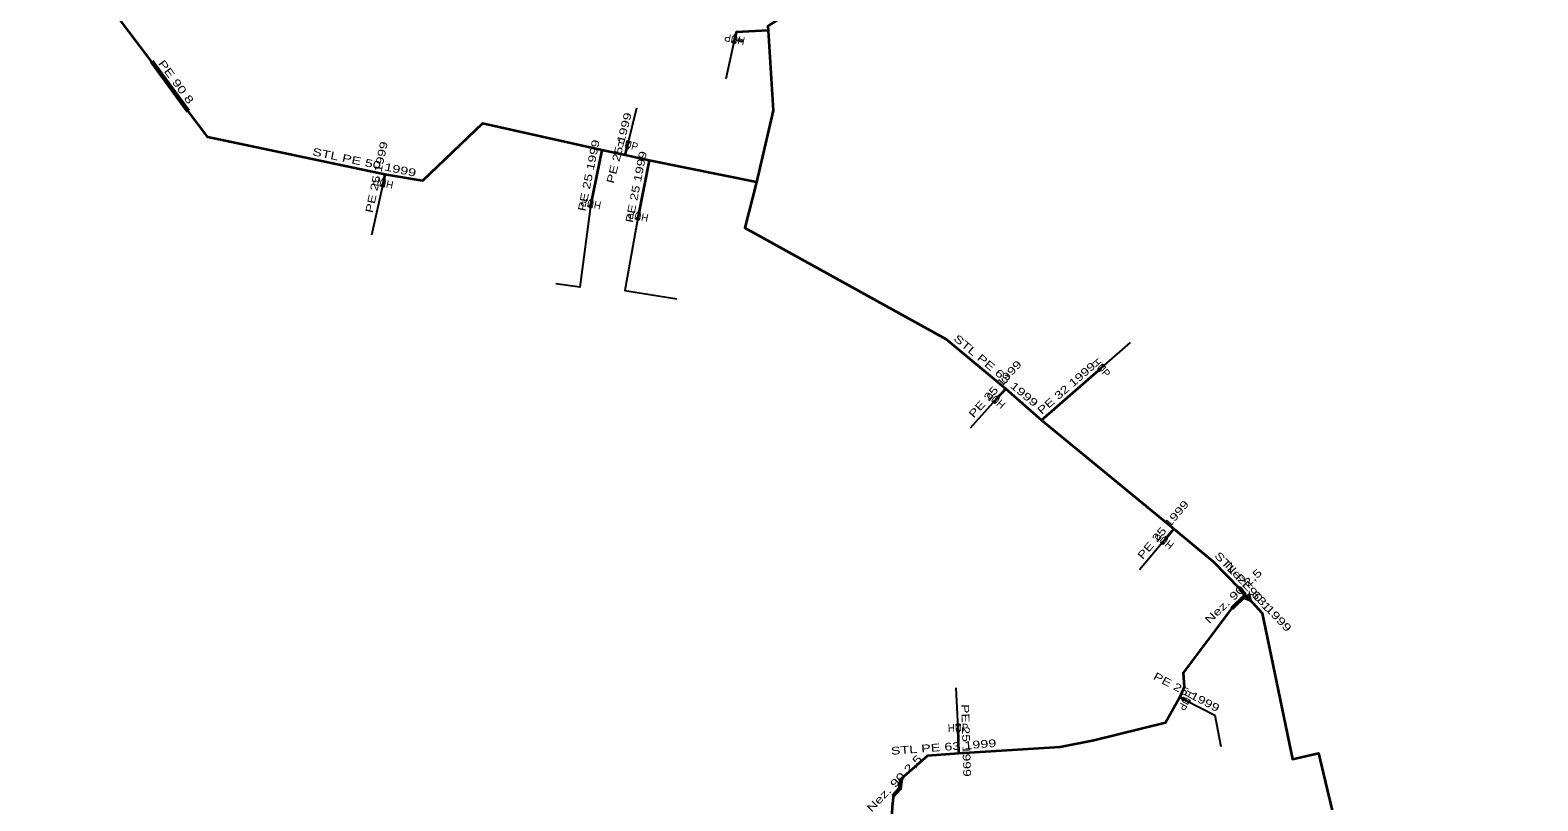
# Model space of a CAD drawing. Extents: x -737484 to -734496, y -1033882 to -1030666.
# Drawn here: x -736285.5 to -736089.6, y -1032119.4 to -1032019.2 of the extents above; entities that cross this region are included whole.
import ezdxf
from ezdxf.enums import TextEntityAlignment as Align

# ---------------------------------------------------------------- set-up
doc = ezdxf.new("R2010")
doc.units = 0
doc.header["$LTSCALE"] = 0.4
for name, color, linetype, lineweight in [('1', 7, 'Continuous', 13), ('18', 7, 'Continuous', 60), ('22', 7, 'Continuous', 25), ('5', 7, 'Continuous', 35), ('7', 7, 'Continuous', 35)]:
    doc.layers.add(name, color=color, linetype=linetype, lineweight=lineweight)
doc.layers.add('2', color=7, linetype='Continuous')

msp = doc.modelspace()

# ---------------------------------------------------------------- linework, layer by layer
at = {"layer": '1'}
for p, q in [((-736193.959, -1032020.389), (-736193.469, -1032020.492)), ((-736193.412, -1032020.581), (-736193.069, -1032020.654))]:
    msp.add_line(p, q, dxfattribs=at)
for points in [[(-736193.867, -1032020.92), (-736194.258, -1032020.837), (-736193.659, -1032019.942), (-736194.05, -1032019.859)], [(-736192.98, -1032020.596), (-736193.012, -1032020.743), (-736193.501, -1032020.639), (-736193.469, -1032020.492)], [(-736192.98, -1032020.596), (-736192.949, -1032020.45), (-736193.438, -1032020.346), (-736193.469, -1032020.492)], [(-736193.025, -1032020.625), (-736193.041, -1032020.698), (-736193.457, -1032020.61), (-736193.441, -1032020.536)], [(-736207.901, -1032033.535), (-736207.512, -1032033.632), (-736208.143, -1032034.505), (-736207.754, -1032034.602)], [(-736239.538, -1032039.599), (-736239.929, -1032039.516), (-736239.33, -1032038.621), (-736239.721, -1032038.538)], [(-736212.538, -1032042.296), (-736212.93, -1032042.22), (-736212.347, -1032041.315), (-736212.739, -1032041.239)], [(-736206.388, -1032043.897), (-736206.78, -1032043.821), (-736206.197, -1032042.916), (-736206.589, -1032042.84)], [(-736146.05, -1032062.6), (-736145.788, -1032062.901), (-736146.805, -1032063.256), (-736146.543, -1032063.557)], [(-736160.184, -1032067.722), (-736160.482, -1032067.454), (-736159.515, -1032066.979), (-736159.813, -1032066.711)], [(-736138.306, -1032086.031), (-736138.612, -1032085.774), (-736137.663, -1032085.265), (-736137.969, -1032085.008)], [(-736127, -1032092.425), (-736127.777, -1032093.055), (-736126.759, -1032093.517)], [(-736127.588, -1032093.03), (-736126.9, -1032093.343), (-736127.063, -1032092.605)], [(-736127.04, -1032093.17), (-736127.126, -1032092.785), (-736127.4, -1032093.007)], [(-736134.753, -1032106.385), (-736134.941, -1032106.738), (-736135.636, -1032105.915), (-736135.824, -1032106.268)], [(-736165.134, -1032109.385), (-736164.734, -1032109.371), (-736165.099, -1032110.384), (-736164.699, -1032110.37)]]:
    msp.add_lwpolyline(points, close=True, dxfattribs=at)
at = {"layer": '18'}
for p, q in [((-736269.709, -1032023.289), (-736264.973, -1032029.736)), ((-736128.289, -1032091.819), (-736127.614, -1032092.557)), ((-736127.549, -1032092.629), (-736129.362, -1032094.35))]:
    msp.add_line(p, q, dxfattribs=at)
msp.add_lwpolyline([(-736172.309, -1032116.499), (-736172.469, -1032117.777), (-736173.4, -1032118.748)], dxfattribs=at)
at = {"layer": '22'}
for p, q in [((-736193.96, -1032020.39), (-736195.111, -1032025.513)), ((-736207.829, -1032034.069), (-736206.675, -1032029.303)), ((-736239.63, -1032039.069), (-736241.135, -1032045.851)), ((-736146.297, -1032063.079), (-736142.534, -1032059.786)), ((-736159.999, -1032067.217), (-736163.348, -1032070.93)), ((-736138.138, -1032085.52), (-736141.364, -1032089.34)), ((-736164.918, -1032109.879), (-736165.15, -1032104.675))]:
    msp.add_line(p, q, dxfattribs=at)
for points in [[(-736212.639, -1032041.769), (-736214.059, -1032052.583), (-736217.176, -1032052.158)], [(-736206.489, -1032043.37), (-736208.215, -1032053.044), (-736201.45, -1032054.107)], [(-736135.289, -1032106.328), (-736131.565, -1032108.236), (-736130.784, -1032112.297)]]:
    msp.add_lwpolyline(points, dxfattribs=at)
at = {"layer": '5'}
msp.add_line((-736127.55, -1032092.63), (-736127.074, -1032093.129), dxfattribs=at)
for points in [[(-736182.915, -1031991.278), (-736179.608, -1032000), (-736179.37, -1032000.63), (-736177.28, -1032006.03), (-736176.88, -1032007.07), (-736185.77, -1032011.07), (-736183.97, -1032014.98), (-736189.65, -1032018.68), (-736189.61, -1032019.23), (-736188.94, -1032029.64), (-736191.11, -1032038.94)], [(-736191.11, -1032038.94), (-736205.06, -1032036.16), (-736208.18, -1032035.44), (-736211.22, -1032034.78), (-736226.74, -1032031.32), (-736234.52, -1032038.77), (-736239.39, -1032037.95), (-736262.41, -1032033.12), (-736264.98, -1032029.73), (-736269.71, -1032023.29), (-736275.62, -1032015.49), (-736282.01, -1032009.67), (-736285.5, -1032008)], [(-736191.11, -1032038.94), (-736192.65, -1032044.87), (-736166.45, -1032059.36), (-736158.73, -1032065.81), (-736154.08, -1032069.89), (-736136.88, -1032084.03), (-736131.78, -1032088.27), (-736128.29, -1032091.82), (-736127.55, -1032092.63)], [(-736127.55, -1032092.63), (-736129.33, -1032094.32), (-736135.68, -1032102.73), (-736135.55, -1032104.58), (-736136.09, -1032105.91), (-736137.95, -1032109.21), (-736147.28, -1032111.54), (-736151.67, -1032112.4), (-736164.82, -1032113.22), (-736168.91, -1032113.53), (-736172.31, -1032116.5), (-736172.49, -1032117.77), (-736173.31, -1032118.56), (-736173.49, -1032120.09), (-736173.65, -1032124.08), (-736173.76, -1032125.5), (-736173.69, -1032127.68), (-736173.33, -1032136.09), (-736172.59, -1032147.96), (-736171.5, -1032158.59)], [(-736127.074, -1032093.129), (-736125.39, -1032094.99), (-736121.45, -1032113.97), (-736118.08, -1032113.18), (-736114.16, -1032129.74), (-736113.45, -1032133.45), (-736113.75, -1032142.44), (-736113.83, -1032147.94), (-736112.8, -1032153.07), (-736108.44, -1032174.65), (-736104.7, -1032193.05), (-736103.84, -1032197.45), (-736102.83, -1032201.73), (-736098.84, -1032214.78), (-736097.14, -1032223.44), (-736096.83, -1032225.37), (-736095.05, -1032238.02), (-736094.44, -1032246.92), (-736092.43, -1032254.14), (-736089.76, -1032259.84), (-736089.579, -1032260.239)]]:
    msp.add_lwpolyline(points, dxfattribs=at)
at = {"layer": '7'}
for p, q in [((-736211.22, -1032034.78), (-736212.639, -1032041.768)), ((-736208.18, -1032035.44), (-736207.828, -1032034.069)), ((-736205.06, -1032036.16), (-736206.489, -1032043.369)), ((-736239.39, -1032037.95), (-736239.63, -1032039.069)), ((-736154.08, -1032069.89), (-736146.297, -1032063.079)), ((-736158.73, -1032065.81), (-736159.999, -1032067.217)), ((-736136.88, -1032084.03), (-736138.138, -1032085.52)), ((-736136.09, -1032105.91), (-736135.289, -1032106.327)), ((-736164.82, -1032113.22), (-736164.917, -1032109.878))]:
    msp.add_line(p, q, dxfattribs=at)
msp.add_lwpolyline([(-736189.61, -1032019.23), (-736193.76, -1032019.45), (-736193.959, -1032020.39)], dxfattribs=at)

# ---------------------------------------------------------------- texts
at = {"layer": '18', "width": 1.4}
for s, rotation, p in [('PE 90 8', 306.301, (-736266.9381, -1032026.216)), ('Nez. 90 2,5', 43.509, (-736128.7997, -1032093.1266)), ('Nez. 90 1', 312.447, (-736127.5818, -1032091.85)), ('Nez. 90 2,5', 46.205, (-736172.8495, -1032117.451))]:
    msp.add_text(s, height=1, rotation=rotation, dxfattribs=at).set_placement(p, align=Align.CENTER)
at = {"layer": '2', "width": 0.95}
for rotation, p in [(168, (-736193.8545, -1032019.9002)), (346, (-736207.9485, -1032034.554)), (168, (-736239.5255, -1032038.5792)), (169, (-736212.5431, -1032041.2769)), (169, (-736206.3931, -1032042.8779)), (311, (-736146.6734, -1032063.4065)), (138, (-736159.6639, -1032066.8453)), (140, (-736137.8161, -1032085.1364)), (242, (-736135.73, -1032106.0918)), (2, (-736164.8989, -1032110.3767))]:
    msp.add_text('HUP', height=1, rotation=rotation, dxfattribs=at).set_placement(p, align=Align.CENTER)
at = {"layer": '5', "width": 1.4}
for s, rotation, p in [('STL PE 50 1999', 348.15, (-736242.1817, -1032036.8528)), ('STL PE 63 1999', 320.122, (-736160.3146, -1032063.8341)), ('STL PE 63 1999', 313.649, (-736126.9503, -1032092.5339)), ('STL PE 63 1999', 4.334, (-736166.7703, -1032112.8663))]:
    msp.add_text(s, height=1, rotation=rotation, dxfattribs=at).set_placement(p, align=Align.CENTER)
at = {"layer": '7', "width": 1.35}
for s, rotation, p in [('PE 25 1999', 75.601, (-736208.4876, -1032034.6298)), ('PE 25 1999', 77.895, (-736239.9986, -1032038.4039)), ('PE 25 1999', 78.521, (-736212.419, -1032038.174)), ('PE 25 1999', 78.788, (-736206.2649, -1032039.6667)), ('PE 25 1999', 47.952, (-736159.7349, -1032066.1784)), ('PE 32 1999', 41.19, (-736150.5178, -1032066.1078)), ('PE 25 1999', 49.826, (-736137.89, -1032084.4521)), ('PE 25 1999', 332.499, (-736135.4584, -1032105.674)), ('PE 25 1999', 271.663, (-736164.3678, -1032111.534))]:
    msp.add_text(s, height=1, rotation=rotation, dxfattribs=at).set_placement(p, align=Align.CENTER)

doc.saveas('drawing.dxf')
